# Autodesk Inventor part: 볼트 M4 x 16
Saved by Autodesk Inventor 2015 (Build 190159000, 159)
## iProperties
Created: 2025-08
Part Number: 볼트 M4 x 16
Material: 일반
Document SubType Name: Modeling
Designer: user
Density: 1 g/cm^3
Appearance: 기본값
Author: user
Author: jhkim
Description: 6각 소켓 머리 캡 나사
Creation Date: 2025-08-05
Sending System: Autodesk Inventor 2026
Preprocessor: ST-DEVELOPER v20.1
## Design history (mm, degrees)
node "볼트 M4 x 161"
body "Solid1"
node "기준1"
